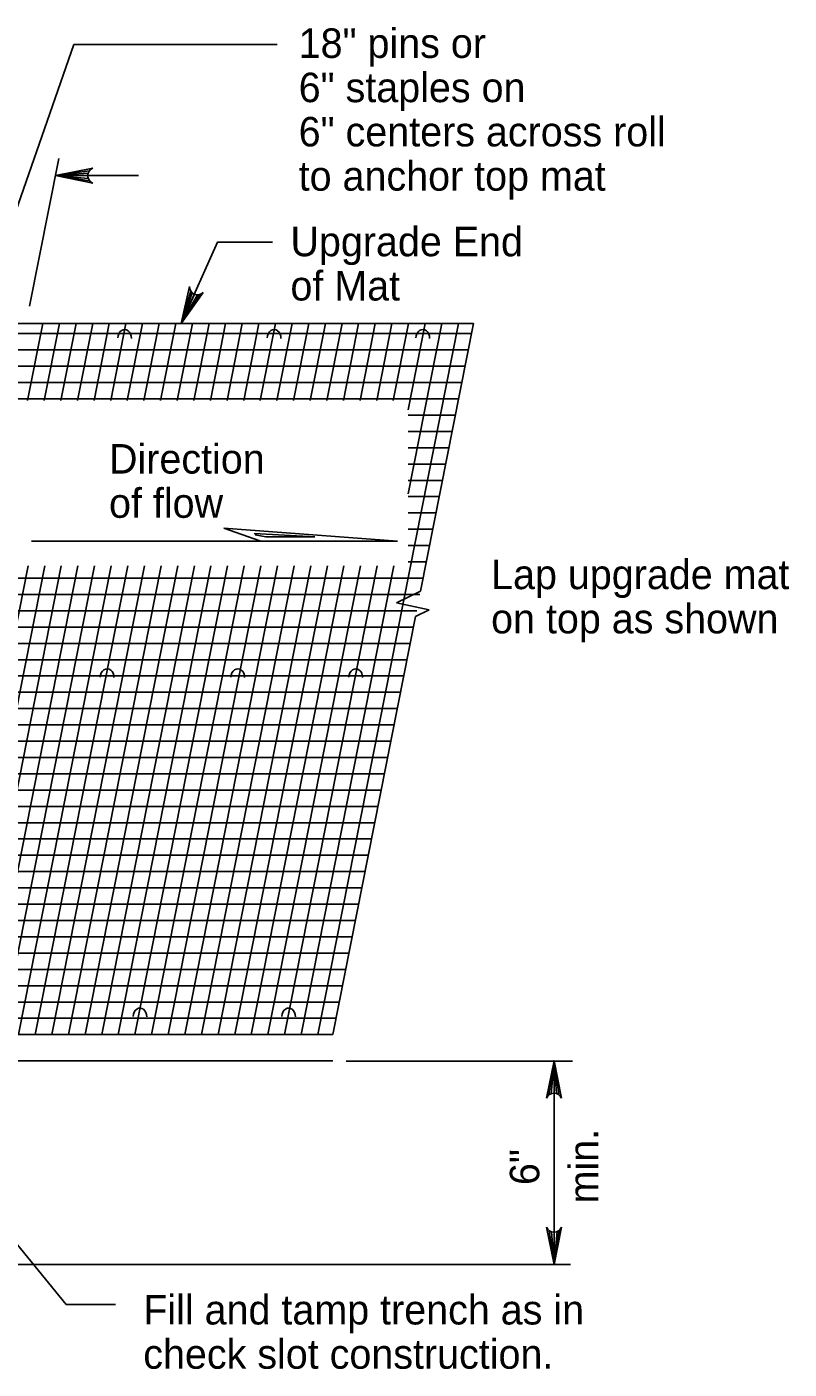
# Model space of a CAD drawing. Extents: x 1083.1 to 1117.1, y 719.4 to 741.4.
# Drawn here: x 1091.75 to 1095.37, y 726.49 to 732.86 of the extents above; entities that cross this region are included whole.
import ezdxf

# ---------------------------------------------------------------- set-up
doc = ezdxf.new("R2010")
doc.units = 0
doc.layers.add('ST_Details', color=7, linetype='Continuous')
doc.layers.add('ST_Text', color=7, linetype='Continuous')

msp = doc.modelspace()

# ---------------------------------------------------------------- linework, layer by layer
at = {"layer": 'ST_Details'}
for p, q in [((1091.5153, 731.4512), (1091.9778, 732.7755)), ((1091.9059, 732.2351), (1091.7672, 731.533)), ((1092.05, 732.1757), (1091.8898, 732.1533)), ((1092.0446, 732.1646), (1091.8898, 732.1533)), ((1091.8898, 732.1533), (1092.2849, 732.1533)), ((1092.0429, 732.1533), (1091.8898, 732.1533)), ((1092.0458, 732.139), (1091.8898, 732.1533)), ((1092.0519, 732.1286), (1091.8898, 732.1533)), ((1092.5317, 731.6065), (1092.486, 731.4512)), ((1092.5395, 731.597), (1092.486, 731.4512)), ((1092.5491, 731.5908), (1092.486, 731.4512)), ((1092.5754, 731.5888), (1092.486, 731.4512)), ((1092.5635, 731.5874), (1092.486, 731.4512)), ((1088.2015, 731.4512), (1093.8736, 731.4512)), ((1090.5547, 731.4031), (1093.8641, 731.4031)), ((1091.2551, 731.4031), (1093.8641, 731.4031)), ((1091.7578, 731.0861), (1091.83, 731.4512)), ((1091.8367, 731.0861), (1091.9088, 731.4512)), ((1091.9156, 731.0861), (1091.9878, 731.4512)), ((1091.9945, 731.0861), (1092.0667, 731.4512)), ((1092.0733, 731.0861), (1092.1455, 731.4512)), ((1092.1523, 731.0861), (1092.2244, 731.4512)), ((1092.2311, 731.0861), (1092.3033, 731.4512)), ((1092.31, 731.0861), (1092.3822, 731.4512)), ((1092.3889, 731.0861), (1092.461, 731.4512)), ((1092.4678, 731.0861), (1092.5399, 731.4512)), ((1092.5466, 731.0861), (1092.6188, 731.4512)), ((1092.6255, 731.0861), (1092.6977, 731.4512)), ((1092.7044, 731.0861), (1092.7766, 731.4512)), ((1092.7833, 731.0861), (1092.8554, 731.4512)), ((1092.8622, 731.0861), (1092.9343, 731.4512)), ((1092.941, 731.0861), (1093.0132, 731.4512)), ((1093.0199, 731.0861), (1093.0921, 731.4512)), ((1093.0988, 731.0861), (1093.1709, 731.4512)), ((1093.1348, 728.076), (1093.802, 731.4512)), ((1093.1777, 731.0861), (1093.2498, 731.4512)), ((1093.2565, 731.0861), (1093.3287, 731.4512)), ((1093.3354, 731.0861), (1093.4076, 731.4512)), ((1093.4143, 731.0861), (1093.4864, 731.4512)), ((1093.4932, 731.0861), (1093.5653, 731.4512)), ((1093.5633, 731.0421), (1093.6443, 731.4512)), ((1093.5633, 730.6429), (1093.7231, 731.4512)), ((1093.6224, 730.1802), (1093.8736, 731.4512)), ((1090.5547, 731.3257), (1093.8488, 731.3257)), ((1090.5547, 731.2484), (1093.8336, 731.2484)), ((1090.5547, 731.171), (1093.8183, 731.171)), ((1090.5547, 731.0936), (1093.803, 731.0936)), ((1093.5633, 731.0162), (1093.7877, 731.0162)), ((1093.5633, 730.9389), (1093.7723, 730.9389)), ((1093.5633, 730.8615), (1093.7571, 730.8615)), ((1093.5633, 730.7841), (1093.7418, 730.7841)), ((1093.5633, 730.7067), (1093.7265, 730.7067)), ((1093.5633, 730.6294), (1093.7112, 730.6294)), ((1093.5633, 730.552), (1093.6959, 730.552)), ((1093.5126, 730.4175), (1092.6892, 730.4801)), ((1092.6892, 730.4801), (1092.8604, 730.4201)), ((1092.833, 730.4539), (1093.1208, 730.4383)), ((1092.8876, 730.4383), (1092.838, 730.4486)), ((1093.1208, 730.4383), (1092.8876, 730.4383)), ((1093.5633, 730.4746), (1093.6806, 730.4746)), ((1091.7764, 730.4175), (1093.5126, 730.4175)), ((1093.5633, 730.3972), (1093.6653, 730.3972)), ((1093.5633, 730.3199), (1093.6501, 730.3199)), ((1091.3207, 728.076), (1091.7603, 730.3003)), ((1091.3995, 728.076), (1091.8392, 730.3003)), ((1091.4784, 728.076), (1091.918, 730.3003)), ((1091.5573, 728.076), (1091.9969, 730.3003)), ((1091.6362, 728.076), (1092.0758, 730.3003)), ((1091.7151, 728.076), (1092.1547, 730.3003)), ((1091.7939, 728.076), (1092.2336, 730.3003)), ((1091.8728, 728.076), (1092.3125, 730.3003)), ((1091.9517, 728.076), (1092.3913, 730.3003)), ((1092.0306, 728.076), (1092.4703, 730.3003)), ((1092.1094, 728.076), (1092.5491, 730.3003)), ((1092.1883, 728.076), (1092.628, 730.3003)), ((1092.2672, 728.076), (1092.7068, 730.3003)), ((1092.3461, 728.076), (1092.7857, 730.3003)), ((1092.4249, 728.076), (1092.8646, 730.3003)), ((1092.5038, 728.076), (1092.9434, 730.3003)), ((1092.5828, 728.076), (1093.0224, 730.3003)), ((1092.6616, 728.076), (1093.1013, 730.3003)), ((1092.7405, 728.076), (1093.1802, 730.3003)), ((1092.8193, 728.076), (1093.259, 730.3003)), ((1092.8983, 728.076), (1093.3379, 730.3003)), ((1092.9771, 728.076), (1093.4168, 730.3003)), ((1093.056, 728.076), (1093.4956, 730.3003)), ((1090.5547, 730.2426), (1093.6348, 730.2426)), ((1090.5547, 730.1651), (1093.6195, 730.1651)), ((1093.6224, 730.1802), (1093.5086, 730.1251)), ((1093.5086, 730.1251), (1093.6632, 730.0915)), ((1090.5547, 730.0878), (1093.6042, 730.0878)), ((1093.2065, 728.076), (1093.5987, 730.0601)), ((1093.6632, 730.0915), (1093.5987, 730.0601)), ((1090.5547, 730.0104), (1093.5889, 730.0104)), ((1090.5547, 729.9331), (1093.5736, 729.9331)), ((1090.5547, 729.8556), (1093.5583, 729.8556)), ((1090.5547, 729.7783), (1093.543, 729.7783)), ((1087.8557, 729.7009), (1093.5277, 729.7009)), ((1090.5547, 729.6236), (1093.5124, 729.6236)), ((1090.5547, 729.5461), (1093.4971, 729.5461)), ((1091.1903, 729.4688), (1093.4819, 729.4688)), ((1090.9304, 729.3914), (1093.4666, 729.3914)), ((1090.8553, 729.3141), (1093.4513, 729.3141)), ((1090.8401, 729.2366), (1093.436, 729.2366)), ((1090.8248, 729.1593), (1093.4207, 729.1593)), ((1090.8096, 729.082), (1093.4054, 729.082)), ((1090.7943, 729.0046), (1093.3901, 729.0046)), ((1090.779, 728.9272), (1093.3748, 728.9272)), ((1090.7637, 728.8498), (1093.3595, 728.8498)), ((1090.7483, 728.7725), (1093.3443, 728.7725)), ((1090.7331, 728.6951), (1093.3289, 728.6951)), ((1090.7178, 728.6177), (1093.3098, 728.6177)), ((1093.3098, 728.6177), (1093.3136, 728.6177)), ((1090.7025, 728.5403), (1093.2984, 728.5403)), ((1090.6872, 728.463), (1093.2831, 728.463)), ((1090.6719, 728.3856), (1093.2678, 728.3856)), ((1090.6566, 728.3082), (1093.2525, 728.3082)), ((1090.6414, 728.2308), (1093.2373, 728.2308)), ((1090.6261, 728.1535), (1093.2219, 728.1535)), ((1093.2219, 728.1535), (1093.2219, 728.1535)), ((1090.6108, 728.076), (1093.2065, 728.076)), ((1091.6234, 727.9517), (1093.2066, 727.9517)), ((1093.2701, 727.9507), (1094.3441, 727.9507)), ((1094.231, 727.7896), (1094.2558, 727.9517)), ((1094.2414, 727.7957), (1094.2558, 727.9517)), ((1094.2558, 727.9517), (1094.2558, 726.9851)), ((1094.2558, 727.7986), (1094.2558, 727.9517)), ((1094.2672, 727.797), (1094.2558, 727.9517)), ((1094.2783, 727.7915), (1094.2558, 727.9517)), ((1094.2334, 727.1454), (1094.2558, 726.9851)), ((1094.2445, 727.14), (1094.2558, 726.9851)), ((1094.2806, 727.1473), (1094.2558, 726.9851)), ((1094.2703, 727.1411), (1094.2558, 726.9851)), ((1094.2558, 727.1383), (1094.2558, 726.9851)), ((1090.694, 726.9851), (1094.3343, 726.9851))]:
    msp.add_line(p, q, dxfattribs=at)
for points in [[(1091.9778, 732.7755), (1092.9418, 732.7755)], [(1092.0668, 732.118), (1091.8898, 732.1533), (1092.0668, 732.1887)], [(1092.486, 731.4512), (1092.6596, 731.8374), (1092.9199, 731.8374)], [(1092.5912, 731.5979), (1092.486, 731.4512), (1092.5267, 731.6271)], [(1094.2204, 727.7747), (1094.2558, 727.9517), (1094.2913, 727.7747)], [(1092.1758, 726.7945), (1091.9414, 726.7945), (1091.4923, 727.3439)], [(1094.2913, 727.1621), (1094.2558, 726.9851), (1094.2204, 727.1621)]]:
    msp.add_lwpolyline(points, dxfattribs=at)
for centre, start, end in [((1092.0811, 732.1534), 112.08782, 247.91395), ((1092.5648, 731.6256), 177.76221, 313.58833), ((1094.2559, 727.7605), 22.08782, 157.91395), ((1094.2558, 727.1764), 202.08782, 337.91395)]:
    msp.add_arc(centre, 0.0382, start, end, dxfattribs=at)
for centre in [(1092.218, 731.3816), (1092.9273, 731.3816), (1093.633, 731.3816), (1092.135, 729.7713), (1092.7549, 729.7713), (1093.3147, 729.7713), (1092.2908, 728.1611), (1092.9965, 728.1611)]:
    msp.add_ellipse(centre, major_axis=(0.0011, 0.041), ratio=0.78812, start_param=4.7124, end_param=7.853993, dxfattribs=at)

# ---------------------------------------------------------------- texts
at = {"layer": 'ST_Text'}
for s, p in [('18" pins or', (1093.0442, 732.7118)), ('6" staples on', (1093.0442, 732.5018)), ('6" centers across roll', (1093.0442, 732.2918)), ('to anchor top mat', (1093.0442, 732.0818)), ('Upgrade End', (1093.0051, 731.7704)), ('of Mat', (1093.0051, 731.5604)), ('Direction', (1092.1443, 730.739)), ('of flow', (1092.1443, 730.529)), ('Lap upgrade mat ', (1093.9572, 730.1905)), ('on top as shown', (1093.9572, 729.9805)), ('Fill and tamp trench as in', (1092.3068, 726.7003)), ('check slot construction.', (1092.3068, 726.4903))]:
    msp.add_text(s, height=0.14, dxfattribs=at).set_placement(p)
for s, p in [('min.', (1094.4658, 727.275)), ('6"', (1094.1858, 727.3621))]:
    msp.add_text(s, height=0.14, rotation=90, dxfattribs=at).set_placement(p)

doc.saveas('drawing.dxf')
